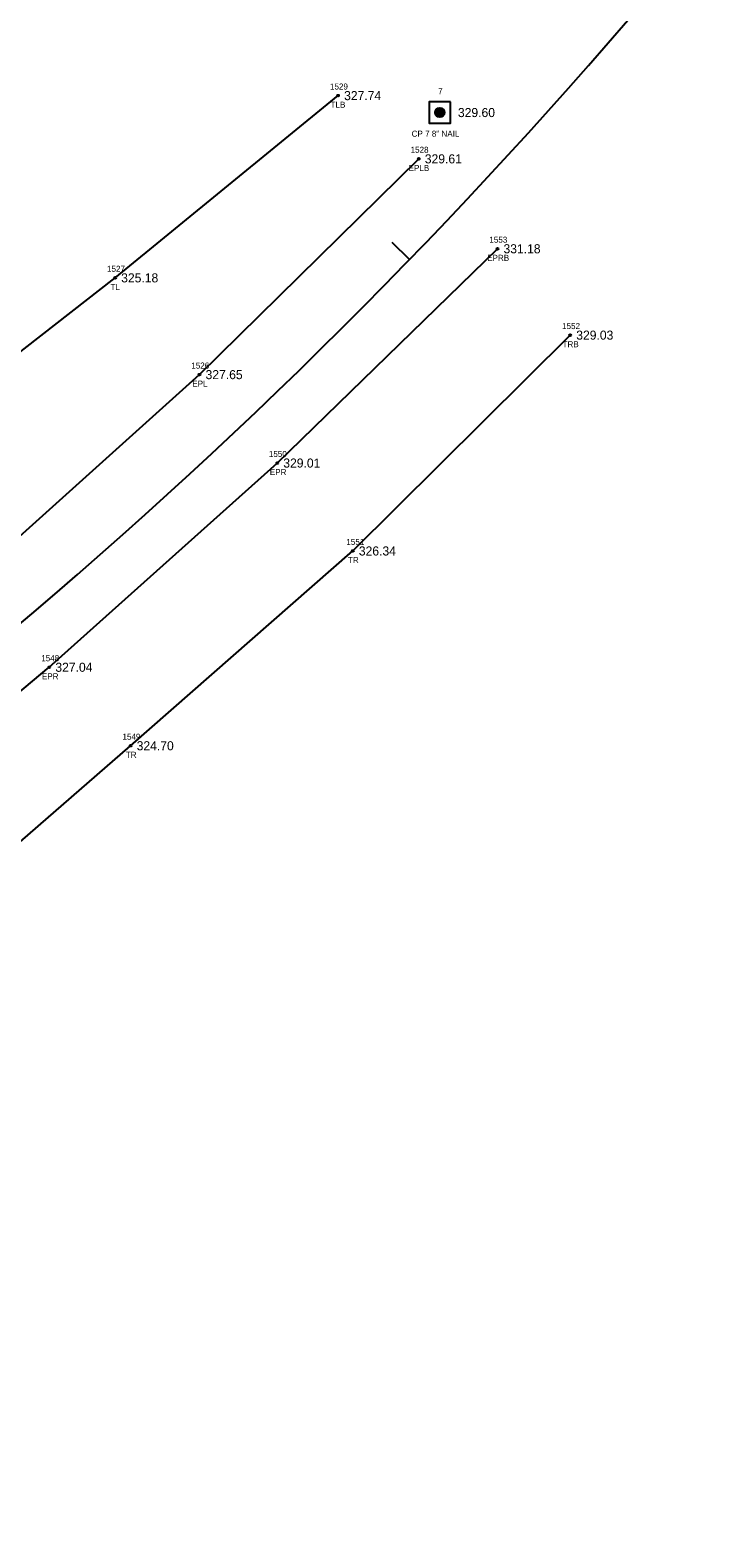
# Model space of a CAD drawing. Extents: x 1865045 to 1867370, y 910391 to 914218.
# Drawn here: x 1866667.2 to 1866779.5, y 913298.4 to 913547.8 of the extents above; entities that cross this region are included whole.
import ezdxf

# ---------------------------------------------------------------- set-up
doc = ezdxf.new("R2010")
doc.units = 0
for name, color, linetype in [('RD_EX_Road', 7, 'Continuous'), ('RD_EX_Road_txCode', 7, 'Continuous'), ('RD_EX_TX_Road_ELEV', 7, 'Continuous'), ('RD_EX_TX_VEG_ELEV', 7, 'Continuous'), ('RD_EX_VEG', 7, 'Continuous'), ('RD_EX_VEG_txCode', 7, 'Continuous'), ('RD_HC_Cl', 7, 'Continuous'), ('RD_HC_Data_Tic', 7, 'Continuous'), ('RD_HC_Survey', 7, 'Continuous'), ('RD_HC_Survey_ELEV', 7, 'Continuous'), ('RD_HC_Survey_txCode', 7, 'Continuous'), ('RD_SMD_Locator', 7, 'Continuous')]:
    doc.layers.add(name, color=color, linetype=linetype)

msp = doc.modelspace()

# ---------------------------------------------------------------- linework, layer by layer
at = {"layer": 'RD_EX_Road'}
for points in [[(1866198.19, 913076.43), (1866191.03, 913082.87), (1866223.86, 913120.42), (1866228.39, 913125.33), (1866247.77, 913145.2), (1866298.81, 913191.9), (1866335.78, 913222.11), (1866414.11, 913280.06), (1866476.76, 913324.36), (1866490.69, 913334.32), (1866499.77, 913340.11), (1866540.97, 913368.88), (1866580.91, 913397.2), (1866621.11, 913427.53), (1866636.38, 913439.8), (1866650.73, 913451.65), (1866658.24, 913457.57), (1866695.23, 913490.79), (1866731.5, 913526.47)], [(1866198.19, 913076.43), (1866206.15, 913069.97), (1866239, 913107.62), (1866272.78, 913142.13), (1866310.33, 913176.03), (1866348.57, 913206.96), (1866383.21, 913233.26), (1866415.26, 913256.44), (1866428.91, 913266.25), (1866510.17, 913323.55), (1866551.75, 913351.73), (1866592.3, 913380.79), (1866633.14, 913411.22), (1866670.38, 913442.4), (1866708.09, 913476.17), (1866744.52, 913511.6)]]:
    msp.add_lwpolyline(points, dxfattribs=at)
at = {"layer": 'RD_EX_VEG'}
for points in [[(1866587.31, 913497.66), (1866624.72, 913462.76), (1866681.27, 913506.79), (1866718.15, 913536.93)], [(1866143.45, 912962.05), (1866201.64, 913035.3), (1866260.86, 913086.64), (1866285.44, 913124.79), (1866318.67, 913163.89), (1866356.27, 913194.75), (1866440.75, 913248.1), (1866521.82, 913312.1), (1866558.81, 913338.62), (1866604.25, 913371.78), (1866643.46, 913394.33), (1866683.83, 913429.42), (1866720.59, 913461.63), (1866756.56, 913497.32)]]:
    msp.add_lwpolyline(points, dxfattribs=at)
at = {"layer": 'RD_HC_Cl'}
msp.add_arc((1866091.29, 914128.71), 889.35, 305.21546, 346.25455, dxfattribs=at)
at = {"layer": 'RD_HC_Data_Tic'}
msp.add_line((1866729.99, 913509.84), (1866727.12, 913512.62), dxfattribs=at)
at = {"layer": 'RD_HC_Survey'}
for p, q in [((1866734.23, 913533.96), (1866734.23, 913534.31)), ((1866734.26, 913533.87), (1866734.26, 913534.4)), ((1866734.28, 913533.81), (1866734.28, 913534.46)), ((1866734.31, 913533.76), (1866734.31, 913534.51)), ((1866734.33, 913533.72), (1866734.33, 913534.55)), ((1866734.36, 913533.68), (1866734.36, 913534.58)), ((1866734.38, 913533.65), (1866734.38, 913534.62)), ((1866734.41, 913533.62), (1866734.41, 913534.65)), ((1866734.43, 913533.6), (1866734.43, 913534.67)), ((1866734.46, 913533.57), (1866734.46, 913534.7)), ((1866734.48, 913533.55), (1866734.48, 913534.72)), ((1866734.51, 913533.53), (1866734.51, 913534.74)), ((1866734.53, 913533.51), (1866734.53, 913534.76)), ((1866734.56, 913533.49), (1866734.56, 913534.77)), ((1866734.58, 913533.48), (1866734.58, 913534.79)), ((1866734.6, 913533.46), (1866734.6, 913534.8)), ((1866734.63, 913533.45), (1866734.63, 913534.82)), ((1866734.65, 913533.44), (1866734.65, 913534.83)), ((1866734.68, 913533.43), (1866734.68, 913534.84)), ((1866734.7, 913533.42), (1866734.7, 913534.85)), ((1866734.73, 913533.41), (1866734.73, 913534.86)), ((1866734.75, 913533.4), (1866734.75, 913534.87)), ((1866734.78, 913533.39), (1866734.78, 913534.88)), ((1866734.8, 913533.39), (1866734.8, 913534.88)), ((1866734.83, 913533.38), (1866734.83, 913534.89)), ((1866734.85, 913533.38), (1866734.85, 913534.89)), ((1866734.88, 913533.37), (1866734.88, 913534.9)), ((1866734.9, 913533.37), (1866734.9, 913534.9)), ((1866734.93, 913533.37), (1866734.93, 913534.9)), ((1866734.95, 913533.37), (1866734.95, 913534.9)), ((1866734.98, 913533.36), (1866734.98, 913534.9)), ((1866735, 913533.36), (1866735, 913534.9)), ((1866735.03, 913533.37), (1866735.03, 913534.9)), ((1866735.05, 913533.37), (1866735.05, 913534.9)), ((1866735.08, 913533.37), (1866735.08, 913534.9)), ((1866735.1, 913533.37), (1866735.1, 913534.89)), ((1866735.12, 913533.38), (1866735.12, 913534.89)), ((1866735.15, 913533.38), (1866735.15, 913534.89)), ((1866735.17, 913533.39), (1866735.17, 913534.88)), ((1866735.2, 913533.4), (1866735.2, 913534.87)), ((1866735.22, 913533.4), (1866735.22, 913534.86)), ((1866735.25, 913533.41), (1866735.25, 913534.86)), ((1866735.27, 913533.42), (1866735.27, 913534.85)), ((1866735.3, 913533.43), (1866735.3, 913534.84)), ((1866735.32, 913533.44), (1866735.32, 913534.82)), ((1866735.35, 913533.46), (1866735.35, 913534.81)), ((1866735.37, 913533.47), (1866735.37, 913534.8)), ((1866735.4, 913533.49), (1866735.4, 913534.78)), ((1866735.42, 913533.5), (1866735.42, 913534.77)), ((1866735.45, 913533.52), (1866735.45, 913534.75)), ((1866735.47, 913533.54), (1866735.47, 913534.73)), ((1866735.5, 913533.56), (1866735.5, 913534.71)), ((1866735.52, 913533.58), (1866735.52, 913534.68)), ((1866735.55, 913533.61), (1866735.55, 913534.66)), ((1866735.57, 913533.64), (1866735.57, 913534.63)), ((1866735.59, 913533.67), (1866735.59, 913534.6)), ((1866735.62, 913533.7), (1866735.62, 913534.56)), ((1866735.64, 913533.74), (1866735.64, 913534.53)), ((1866735.67, 913533.79), (1866735.67, 913534.48)), ((1866735.69, 913533.84), (1866735.69, 913534.43)), ((1866735.72, 913533.91), (1866735.72, 913534.36)), ((1866735.74, 913534.02), (1866735.74, 913534.25))]:
    msp.add_line(p, q, dxfattribs=at)
msp.add_lwpolyline([(1866736.73, 913535.88), (1866733.23, 913535.88), (1866733.23, 913532.38), (1866736.73, 913532.38)], close=True, dxfattribs=at)
msp.add_circle((1866734.98, 913534.13), 0.769, dxfattribs=at)
at = {"layer": 'RD_SMD_Locator'}
for centre in [(1866718.15, 913536.93), (1866734.98, 913534.13), (1866731.5, 913526.47), (1866744.52, 913511.6), (1866681.27, 913506.79), (1866756.56, 913497.32), (1866695.23, 913490.79), (1866708.09, 913476.17), (1866720.59, 913461.63), (1866670.38, 913442.4), (1866683.83, 913429.42)]:
    msp.add_circle(centre, 0.15, dxfattribs=at)

# ---------------------------------------------------------------- texts
at = {"layer": 'RD_EX_Road_txCode'}
for s, p in [('1528', (1866730.15, 913527.47)), ('EPLB', (1866729.82, 913524.47)), ('1553', (1866743.18, 913512.6)), ('EPRB', (1866742.82, 913509.6)), ('1526', (1866693.86, 913491.79)), ('EPL', (1866694.03, 913488.79)), ('1550', (1866706.7, 913477.17)), ('EPR', (1866706.86, 913474.17)), ('1548', (1866669.04, 913443.4)), ('EPR', (1866669.15, 913440.4))]:
    msp.add_text(s, height=1, dxfattribs=at).set_placement(p)
at = {"layer": 'RD_EX_TX_Road_ELEV'}
for s, p in [('329.61', (1866732.5, 913525.72)), ('331.18', (1866745.52, 913510.85)), ('327.65', (1866696.23, 913490.04)), ('329.01', (1866709.09, 913475.42)), ('327.04', (1866671.38, 913441.65))]:
    msp.add_text(s, height=1.5, dxfattribs=at).set_placement(p)
at = {"layer": 'RD_EX_TX_VEG_ELEV'}
for s, p in [('327.74', (1866719.15, 913536.18)), ('325.18', (1866682.27, 913506.04)), ('329.03', (1866757.56, 913496.57)), ('326.34', (1866721.59, 913460.88)), ('324.70', (1866684.83, 913428.67))]:
    msp.add_text(s, height=1.5, dxfattribs=at).set_placement(p)
at = {"layer": 'RD_EX_VEG_txCode'}
for s, p in [('1529', (1866716.81, 913537.93)), ('TLB', (1866716.91, 913534.93)), ('1527', (1866679.92, 913507.79)), ('TL', (1866680.49, 913504.79)), ('1552', (1866755.21, 913498.32)), ('TRB', (1866755.29, 913495.32)), ('1551', (1866719.52, 913462.63)), ('TR', (1866719.79, 913459.63)), ('1549', (1866682.48, 913430.42)), ('TR', (1866683.03, 913427.42))]:
    msp.add_text(s, height=1, dxfattribs=at).set_placement(p)
at = {"layer": 'RD_HC_Survey_ELEV'}
msp.add_text('329.60', height=1.5, dxfattribs=at).set_placement((1866737.98, 913533.38))
at = {"layer": 'RD_HC_Survey_txCode'}
for s, p in [('7', (1866734.7, 913537.13)), ('CP 7 8" NAIL', (1866730.32, 913530.13))]:
    msp.add_text(s, height=1, dxfattribs=at).set_placement(p)

doc.saveas('drawing.dxf')
